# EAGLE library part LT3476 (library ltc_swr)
LT3476 - High Current Quad Output LED Driver True Color PWM Dimming Delivers Up to 1000:1 Dimming Ratio LED Current Regulation with High-Side Sense VADJ Pin Accurately Sets LED Current Sense Threshold Over Range 10mV to 120mV Four Independent Driver Channels with 1.5A, 36V Internal NPN Switches Frequency Adjust Pin: 200kHz to 2MHz High Ef&#64257;ciency Conversion = Up to 96% Open LED Protection Low Quiescent Current 22mA in Active Mode <10&micro;A in Shutdown Mode Wide VIN Range: 2.8V to 16V Thermally Enhanced, 38-Lead, 5mm &times; 7mm QFN Package
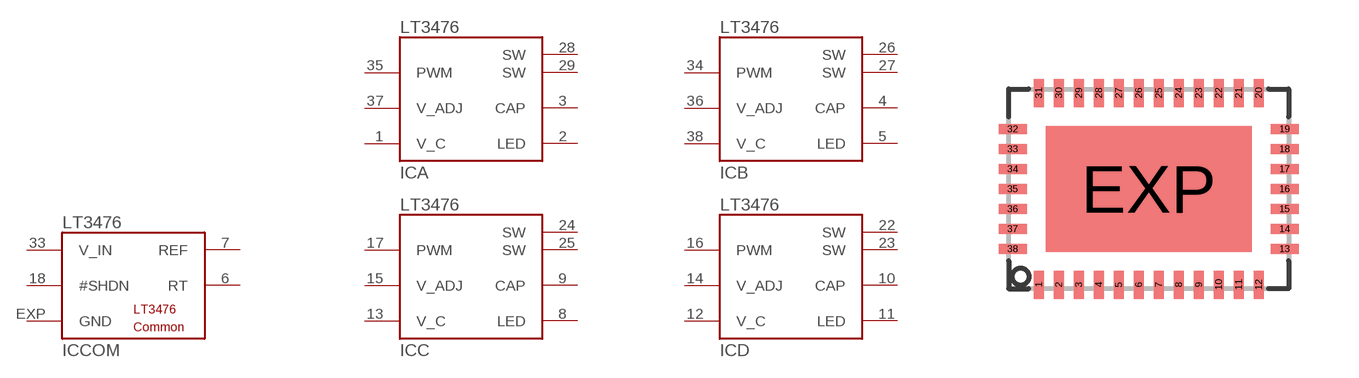
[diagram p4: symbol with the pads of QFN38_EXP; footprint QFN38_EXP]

Designator prefix IC; gates COM=LT3476_COMMON A=LT3476_SWITCH B=LT3476_SWITCH C=LT3476_SWITCH D=LT3476_SWITCH

## LT3476  [QFN38_EXP]
1  A:V_C  pas
2  A:LED  pas
3  A:CAP  pas
4  B:CAP  pas
5  B:LED  pas
6  COM:RT  pas
7  COM:REF  pas
8  C:LED  pas
9  C:CAP  pas
10  D:CAP  pas
11  D:LED  pas
12  D:V_C  pas
13  C:V_C  pas
14  D:V_ADJ  pas
15  C:V_ADJ  pas
16  D:PWM  pas
17  C:PWM  pas
18  COM:#SHDN  pas
22  D:SW  pas
23  D:SW  pas
24  C:SW  pas
25  C:SW  pas
26  B:SW  pas
27  B:SW  pas
28  A:SW  pas
29  A:SW  pas
33  COM:V_IN  pas
34  B:PWM  pas
35  A:PWM  pas
36  B:V_ADJ  pas
37  A:V_ADJ  pas
38  B:V_C  pas
EXP  COM:GND  pas

## Footprint QFN38_EXP (pad centres in mm)
smd 0.25 x 0.7: 1 -2.75,-2.4; 2 -2.25,-2.4; 3 -1.75,-2.4; 4 -1.25,-2.4; 5 -0.75,-2.4; 6 -0.25,-2.4; 7 0.25,-2.4; 8 0.75,-2.4; 9 1.25,-2.4; 10 1.75,-2.4; 11 2.25,-2.4; 12 2.75,-2.4; 20 2.75,2.4; 21 2.25,2.4; 22 1.75,2.4; 23 1.25,2.4; 24 0.75,2.4; 25 0.25,2.4; 26 -0.25,2.4; 27 -0.75,2.4; 28 -1.25,2.4; 29 -1.75,2.4; 30 -2.25,2.4; 31 -2.75,2.4
smd 0.7 x 0.25: 13 3.4,-1.5; 14 3.4,-1; 15 3.4,-0.5; 16 3.4,0; 17 3.4,0.5; 18 3.4,1; 19 3.4,1.5; 32 -3.4,1.5; 33 -3.4,1; 34 -3.4,0.5; 35 -3.4,0; 36 -3.4,-0.5; 37 -3.4,-1; 38 -3.4,-1.5
smd 5.15 x 3.15: EXP 0,0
